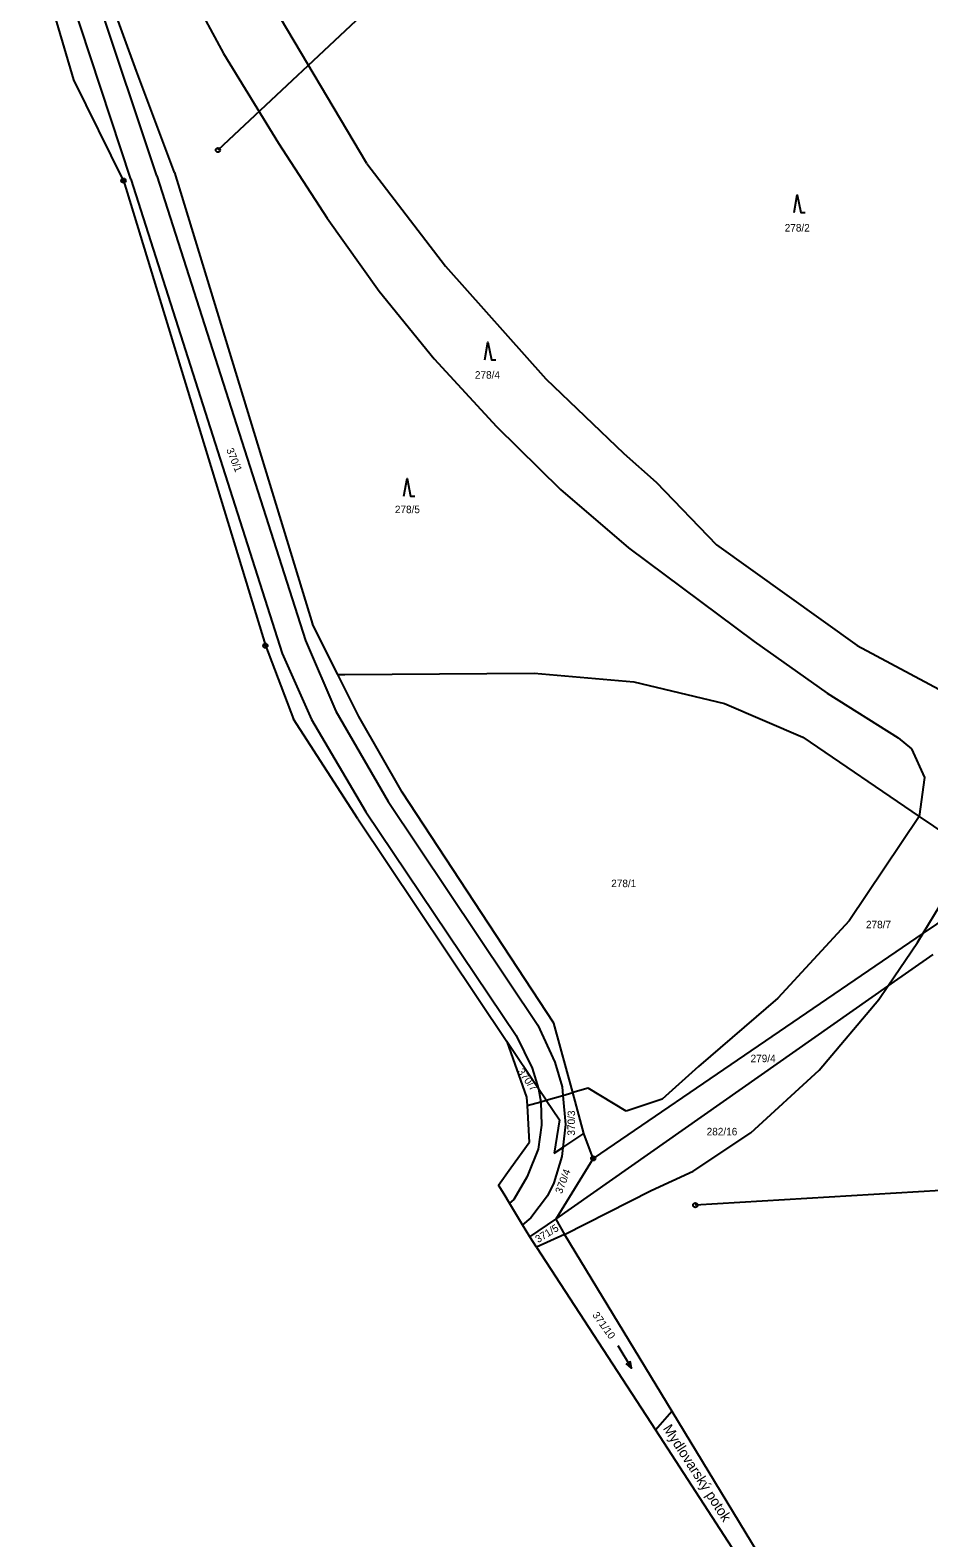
# Model space of a CAD drawing. Extents: x -762263 to -760336, y -1154405 to -1152076.
# Drawn here: x -762196.3 to -761992.3, y -1152903.3 to -1152561.1 of the extents above; entities that cross this region are included whole.
import ezdxf

# ---------------------------------------------------------------- set-up
doc = ezdxf.new("R2010")
doc.units = 0
for name, color, linetype in [('Vrstva 1', 7, 'Continuous'), ('Vrstva 12', 7, 'Continuous'), ('Vrstva 13', 7, 'Continuous'), ('Vrstva 15', 7, 'Continuous'), ('Vrstva 18', 7, 'Continuous'), ('Vrstva 24', 7, 'Continuous'), ('Vrstva 25', 7, 'Continuous'), ('Vrstva 26', 7, 'Continuous'), ('Vrstva 4', 7, 'Continuous'), ('Vrstva 6', 7, 'Continuous')]:
    doc.layers.add(name, color=color, linetype=linetype)

msp = doc.modelspace()

# ---------------------------------------------------------------- linework, layer by layer
at = {"layer": 'Vrstva 1'}
for p, q in [((-762172.17, -1152570.43), (-762185.55, -1152533.53)), ((-762162.8, -1152547.22), (-762152.37, -1152566.39)), ((-762119.86, -1152591.38), (-762142.3, -1152553.42)), ((-762152.37, -1152566.39), (-762139.93, -1152586.76)), ((-762163.53, -1152593.42), (-762172.17, -1152570.43)), ((-762139.93, -1152586.76), (-762128.87, -1152603.79)), ((-762163.53, -1152593.42), (-762132.18, -1152695.9)), ((-762119.86, -1152591.38), (-762101.99, -1152614.67)), ((-762128.87, -1152603.79), (-762117.09, -1152620.36)), ((-762101.99, -1152614.67), (-762079.19, -1152640.25)), ((-762117.09, -1152620.36), (-762104.55, -1152635.68)), ((-762104.55, -1152635.68), (-762090.39, -1152651.07)), ((-762079.19, -1152640.25), (-762061.55, -1152657.19)), ((-762090.39, -1152651.07), (-762075.87, -1152665.35)), ((-762061.55, -1152657.19), (-762054.17, -1152663.66)), ((-762075.87, -1152665.35), (-762060.42, -1152678.6)), ((-762054.17, -1152663.66), (-762040.49, -1152677.91)), ((-762060.42, -1152678.6), (-762031.94, -1152699.84)), ((-762040.49, -1152677.91), (-762008.53, -1152700.8)), ((-762126.45, -1152707.38), (-762132.18, -1152695.9)), ((-762031.94, -1152699.84), (-762015.35, -1152711.55)), ((-762008.53, -1152700.8), (-761978.76, -1152716.74)), ((-762124.83, -1152707.37), (-762081.9, -1152707.06)), ((-762081.9, -1152707.06), (-762059.28, -1152709.01)), ((-762126.45, -1152707.38), (-762124.83, -1152707.37)), ((-762121.7, -1152716.89), (-762126.45, -1152707.38)), ((-762059.28, -1152709.01), (-762038.66, -1152713.96)), ((-762038.66, -1152713.96), (-762020.85, -1152721.61)), ((-762015.35, -1152711.55), (-761999.25, -1152721.69)), ((-762111.83, -1152734.04), (-762121.7, -1152716.89)), ((-762020.85, -1152721.61), (-761994.44, -1152739.57)), ((-761999.25, -1152721.69), (-761996.2, -1152724.25)), ((-761996.2, -1152724.25), (-761993.26, -1152730.75)), ((-761993.26, -1152730.75), (-761994.44, -1152739.57)), ((-762077.39, -1152786.46), (-762111.83, -1152734.04)), ((-761994.44, -1152739.57), (-762010.35, -1152763.28)), ((-761994.44, -1152739.57), (-761982.68, -1152747.59)), ((-761974.57, -1152753.12), (-761993.53, -1152766.06)), ((-761993.53, -1152766.06), (-761985.87, -1152753.36)), ((-762010.35, -1152763.28), (-762026.58, -1152780.83)), ((-761993.53, -1152766.06), (-762068.45, -1152817.19)), ((-762001.57, -1152778.08), (-761994.83, -1152768.21)), ((-761994.83, -1152768.21), (-761993.53, -1152766.06)), ((-762001.57, -1152778.08), (-761991.29, -1152770.87)), ((-762076.97, -1152830.96), (-762001.57, -1152778.08)), ((-762003.64, -1152781.11), (-762001.57, -1152778.08)), ((-762026.58, -1152780.83), (-762044.58, -1152796.35)), ((-762017.17, -1152797.15), (-762003.64, -1152781.11)), ((-762073.11, -1152802.26), (-762077.39, -1152786.46)), ((-762044.58, -1152796.35), (-762052.83, -1152803.75)), ((-762032.67, -1152811.41), (-762017.17, -1152797.15)), ((-762079.18, -1152803.98), (-762075.35, -1152802.89)), ((-762075.35, -1152802.89), (-762073.11, -1152802.26)), ((-762069.6, -1152801.26), (-762073.11, -1152802.26)), ((-762070.59, -1152811.54), (-762073.11, -1152802.26)), ((-762060.95, -1152806.45), (-762069.6, -1152801.26)), ((-762083.44, -1152805.2), (-762080.37, -1152804.32)), ((-762080.37, -1152804.32), (-762079.18, -1152803.98)), ((-762079.18, -1152803.98), (-762076.15, -1152808.46)), ((-762052.83, -1152803.75), (-762060.95, -1152806.45)), ((-762076.15, -1152808.46), (-762077.3, -1152816)), ((-762075.34, -1152814.7), (-762070.59, -1152811.54)), ((-762068.45, -1152817.19), (-762070.59, -1152811.54)), ((-762045.81, -1152820.07), (-762032.67, -1152811.41)), ((-762077.3, -1152816), (-762075.34, -1152814.7)), ((-762068.45, -1152817.19), (-762076.97, -1152830.96)), ((-762055.28, -1152824.45), (-762045.81, -1152820.07)), ((-762075.01, -1152834.45), (-762055.28, -1152824.45)), ((-762082.89, -1152834.96), (-762076.97, -1152830.96)), ((-762076.97, -1152830.96), (-762075.01, -1152834.45)), ((-762075.01, -1152834.45), (-762081.34, -1152837.33)), ((-762075.01, -1152834.45), (-762050.65, -1152874.54)), ((-762054.35, -1152878.82), (-762050.65, -1152874.54)), ((-762050.65, -1152874.54), (-762026.45, -1152914.36))]:
    msp.add_line(p, q, dxfattribs=at)
at = {"layer": 'Vrstva 12'}
for p, q in [((-762075.84, -1152515.3), (-762153.67, -1152588.32)), ((-761961.09, -1152822.73), (-762045.29, -1152827.8))]:
    msp.add_line(p, q, dxfattribs=at)
at = {"layer": 'Vrstva 13'}
for p, q in [((-762186.41, -1152572.39), (-762196.29, -1152538.57)), ((-762175.1, -1152595.25), (-762186.41, -1152572.39)), ((-762175.1, -1152595.25), (-762142.88, -1152700.8)), ((-762142.88, -1152700.8), (-762136.49, -1152717.47)), ((-762121.93, -1152740.13), (-762136.49, -1152717.47)), ((-762121.93, -1152740.13), (-762088.07, -1152790.67)), ((-762088.07, -1152790.67), (-762083.58, -1152803.27)), ((-762083.58, -1152803.27), (-762083.44, -1152805.2)), ((-762083.44, -1152805.2), (-762083.02, -1152813.56)), ((-762087.16, -1152819.32), (-762083.02, -1152813.56)), ((-762089.96, -1152823.23), (-762087.16, -1152819.32)), ((-762088.7, -1152825.32), (-762089.96, -1152823.23)), ((-762087.47, -1152827.36), (-762088.7, -1152825.32)), ((-762084.51, -1152832.28), (-762087.47, -1152827.36)), ((-762082.89, -1152834.96), (-762084.51, -1152832.28)), ((-762081.34, -1152837.33), (-762082.89, -1152834.96)), ((-762081.34, -1152837.33), (-762054.35, -1152878.82)), ((-762054.35, -1152878.82), (-762029.76, -1152916.6))]:
    msp.add_line(p, q, dxfattribs=at)
at = {"layer": 'Vrstva 24'}
for centre, radius in [((-762175.1, -1152595.25), 0.5), ((-762175.1, -1152595.25), 0.1), ((-762142.88, -1152700.8), 0.5), ((-762142.88, -1152700.8), 0.1), ((-762068.45, -1152817.19), 0.5), ((-762068.45, -1152817.19), 0.1)]:
    msp.add_circle(centre, radius, dxfattribs=at)
at = {"layer": 'Vrstva 25'}
for points in [[(-762022.84, -1152602.51), (-762022.14, -1152598.51), (-762021.34, -1152602.51), (-762020.34, -1152602.51)], [(-762093.06, -1152635.94), (-762092.36, -1152631.94), (-762091.56, -1152635.94), (-762090.56, -1152635.94)], [(-762111.43, -1152666.85), (-762110.73, -1152662.85), (-762109.93, -1152666.85), (-762108.93, -1152666.85)], [(-762062.912, -1152859.671), (-762059.748, -1152864.769), (-762060.114, -1152863.231)], [(-762059.748, -1152864.769), (-762060.964, -1152863.758)]]:
    msp.add_lwpolyline(points, dxfattribs=at)
at = {"layer": 'Vrstva 26'}
for centre in [(-762153.67, -1152588.32), (-762045.29, -1152827.8)]:
    msp.add_circle(centre, 0.5, dxfattribs=at)
at = {"layer": 'Vrstva 4'}
for p, q in [((-762173.44, -1152594.91), (-762194.68, -1152530.57)), ((-762167.51, -1152594.17), (-762188.97, -1152529.85)), ((-762167.51, -1152594.17), (-762133.77, -1152699.64)), ((-762173.44, -1152594.91), (-762139.08, -1152702.6)), ((-762133.77, -1152699.64), (-762126.89, -1152715.68)), ((-762139.08, -1152702.6), (-762132.41, -1152717.58)), ((-762126.89, -1152715.68), (-762115.01, -1152736.15)), ((-762132.41, -1152717.58), (-762120.12, -1152738.53)), ((-762115.01, -1152736.15), (-762081.04, -1152786.96)), ((-762120.12, -1152738.53), (-762085.97, -1152789.27)), ((-762085.97, -1152789.27), (-762082.34, -1152796.67)), ((-762081.04, -1152786.96), (-762077.19, -1152795.35)), ((-762077.19, -1152795.35), (-762075.52, -1152800.91)), ((-762082.34, -1152796.67), (-762080.9, -1152801.4)), ((-762080.9, -1152801.4), (-762080.37, -1152804.32)), ((-762075.52, -1152800.91), (-762075.35, -1152802.89)), ((-762075.35, -1152802.89), (-762074.79, -1152809.49)), ((-762080.37, -1152804.32), (-762080.22, -1152809.63)), ((-762080.22, -1152809.63), (-762080.94, -1152815.1)), ((-762074.79, -1152809.49), (-762075.34, -1152814.7)), ((-762080.94, -1152815.1), (-762083.32, -1152820.92)), ((-762075.56, -1152816.72), (-762077.4, -1152822.7)), ((-762075.34, -1152814.7), (-762075.56, -1152816.72)), ((-762083.54, -1152821.46), (-762086.48, -1152826.51)), ((-762083.32, -1152820.92), (-762083.54, -1152821.46)), ((-762077.4, -1152822.7), (-762078.86, -1152825.69)), ((-762086.48, -1152826.51), (-762087.47, -1152827.36)), ((-762078.86, -1152825.69), (-762082.66, -1152830.66)), ((-762082.66, -1152830.66), (-762084.51, -1152832.28))]:
    msp.add_line(p, q, dxfattribs=at)
at = {"layer": 'Vrstva 6'}
for p, q in [((-762080.9, -1152801.4), (-762088.07, -1152790.67)), ((-762079.18, -1152803.98), (-762080.9, -1152801.4))]:
    msp.add_line(p, q, dxfattribs=at)

# ---------------------------------------------------------------- texts
at = {"layer": 'Vrstva 15'}
msp.add_text('Mydlovarský potok', height=2.3, rotation=302.86549, dxfattribs=at).set_placement((-762052.73, -1152878.5))
at = {"layer": 'Vrstva 18'}
for s, p in [('278/2', (-762024.993, -1152606.8)), ('278/4', (-762095.323, -1152640.2)), ('278/5', (-762113.493, -1152670.73)), ('278/1', (-762064.383, -1152755.62)), ('278/7', (-762006.553, -1152764.96)), ('279/4', (-762032.743, -1152795.35)), ('282/16', (-762042.713, -1152811.95))]:
    msp.add_text(s, height=1.7, dxfattribs=at).set_placement(p)
for s, rotation, p in [('370/1', 292.09388, (-762151.808, -1152656.323)), ('370/7', 305.84487, (-762085.75, -1152797.49)), ('370/3', 89.49601, (-762072.628, -1152812.023)), ('370/4', 69.15601, (-762075.588, -1152825.337)), ('371/5', 31.56998, (-762080.978, -1152836.426)), ('371/10', 305.95946, (-762068.765, -1152852.757))]:
    msp.add_text(s, height=1.7, rotation=rotation, dxfattribs=at).set_placement(p)

doc.saveas('drawing.dxf')
